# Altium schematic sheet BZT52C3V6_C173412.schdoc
size 127 x 101 mm
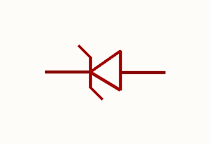
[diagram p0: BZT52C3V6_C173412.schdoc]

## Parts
D?  bzt52c3v6_c173412  [SOD-123_L2.7-W1.6-LS3.7-RD]  (value not drawn)

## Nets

Not connected (* = marked no-connect by the designer): D? 1(C) 2(A)

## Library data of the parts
D? = bzt52c3v6_c173412: 二极管配置:1个独立式;稳压值(标称值):3.6V;稳压值(范围):3.42V~3.78V;耗散功率(Pd):500mW;; Manufacturer: MDD(辰达半导体); AddInBom: yes; ModelId: ad7e39f9e5534b3c96ffdc5532ebb493; ModelName: SOD-123_L2.7-W1.6-H1.4-LS3.7; ModelTransform: 146.026,62.992,0,180,0,0,0.0005,0,0; Diode Configuration: 1个独立式; Zener Voltage(Nom): 3.6V; Reverse Leakage Current (Ir): 10uA@1V; Pd - Power Dissipation: 500mW; Impedance(Zzt): 130Ω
